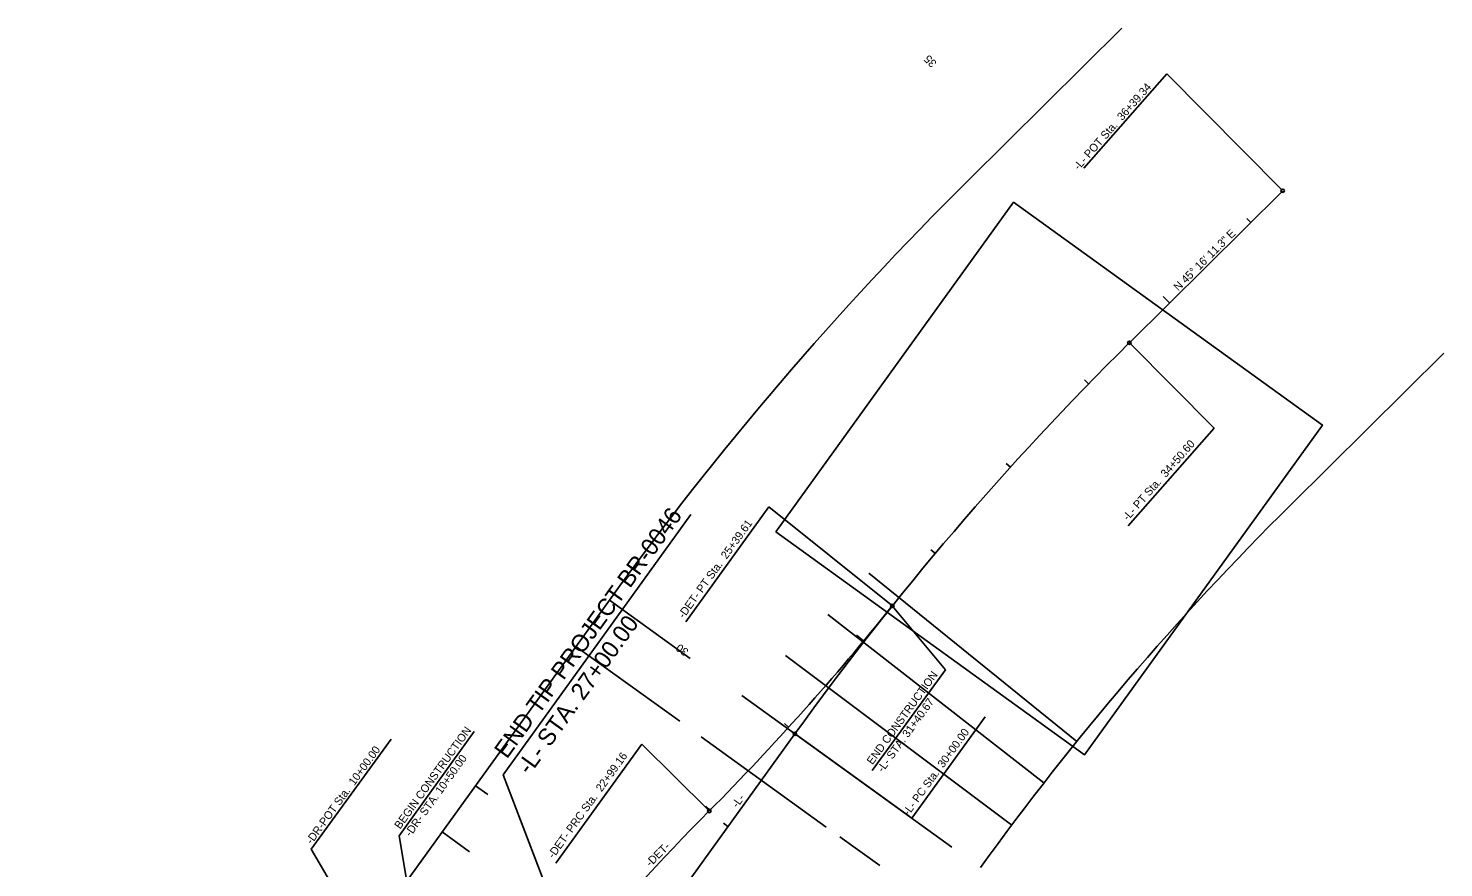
# Model space of a CAD drawing. Extents: x 2189281 to 2191267, y 386656 to 389012.
# Drawn here: x 2190029 to 2191267, y 388278 to 389012 of the extents above; entities that cross this region are included whole.
import ezdxf

# ---------------------------------------------------------------- set-up
doc = ezdxf.new("R2010")
doc.units = 0
for name, color, linetype in [('Prop DSN Text', 7, 'Continuous'), ('Prop Horizontal Alignment', 7, 'Continuous'), ('Prop Horizontal Alignment Direction Label', 7, 'Continuous'), ('Prop Horizontal Alignment Station Label', 7, 'Continuous'), ('Prop Horizontal Alignment Tick Label', 7, 'Continuous'), ('Prop Horizontal Alignment Tick Large', 7, 'Continuous'), ('Prop Horizontal Alignment Tick Small', 7, 'Continuous'), ('Scratch_Level_3', 7, 'Continuous'), ('Scratch_Level_5', 7, 'Continuous')]:
    doc.layers.add(name, color=color, linetype=linetype)

msp = doc.modelspace()

# ---------------------------------------------------------------- linework, layer by layer
at = {"layer": 'Prop DSN Text'}
for p, q in [((2190608.2, 388587.1), (2190444, 388359.4)), ((2190830.8, 388451.2), (2190784.4, 388507.2)), ((2190766.7, 388363.2), (2190830.8, 388451.2)), ((2190353.3, 388306), (2190418.9, 388397.4)), ((2190523.8, 388151.9), (2190444, 388359.4)), ((2190374.3, 388178.9), (2190353.3, 388306))]:
    msp.add_line(p, q, dxfattribs=at)
at = {"layer": 'Prop Horizontal Alignment'}
for p, q in [((2190991.7, 388737.3), (2191125.8, 388870.2)), ((2189529.4, 386773.1), (2190699.2, 388395.3))]:
    msp.add_line(p, q, dxfattribs=at)
for centre, radius, start, end in [((2192910.1, 386800.9), 2725.8, 134.7302, 144.2018), ((2188990.8, 389947), 2300, 315.255, 321.245), ((2192257.9, 386708.8), 2300, 135.255, 144.2018)]:
    msp.add_arc(centre, radius, start, end, dxfattribs=at)
at = {"layer": 'Prop Horizontal Alignment Station Label'}
for p, q in [((2190951.9, 388889.9), (2191024.5, 388972.5)), ((2191124.8, 388871.2), (2191024.5, 388972.5)), ((2190992.8, 388736.3), (2191065.8, 388662.6)), ((2190990.8, 388577.1), (2191065.8, 388662.6)), ((2190676.4, 388593.9), (2190603.8, 388493.2)), ((2190783.3, 388508.1), (2190676.4, 388593.9)), ((2190801.4, 388321.6), (2190865.6, 388410.3)), ((2190490.3, 388282.2), (2190565.3, 388386.4)), ((2190623.3, 388328.9), (2190565.3, 388386.4)), ((2190700.5, 388394.4), (2190801.4, 388321.6))]:
    msp.add_line(p, q, dxfattribs=at)
msp.add_lwpolyline([(2190330.1, 388202.3), (2190276.3, 388294.6), (2190346.2, 388390.8)], dxfattribs=at)
for centre in [(2191125.8, 388870.2), (2190991.7, 388737.3), (2190784.4, 388507.2), (2190699.2, 388395.3), (2190624.4, 388327.9)]:
    msp.add_circle(centre, 1.5, dxfattribs=at)
at = {"layer": 'Prop Horizontal Alignment Tick Large'}
for p, q in [((2191026.8, 388772.1), (2191021.2, 388777.8)), ((2190759.4, 388476.5), (2190753.2, 388481.6)), ((2190699.2, 388395.3), (2190692.7, 388400))]:
    msp.add_line(p, q, dxfattribs=at)
at = {"layer": 'Prop Horizontal Alignment Tick Small'}
for p, q in [((2191097.9, 388842.5), (2191094.4, 388846)), ((2190956.1, 388701.4), (2190952.5, 388704.9)), ((2190887.7, 388628.5), (2190884, 388631.8)), ((2190822.1, 388553.1), (2190818.2, 388556.3)), ((2190759.2, 388475.3), (2190755.3, 388478.4)), ((2190693.8, 388401), (2190690.1, 388404.4)), ((2190625, 388328.5), (2190621.4, 388332)), ((2190640.7, 388314.2), (2190636.7, 388317.1))]:
    msp.add_line(p, q, dxfattribs=at)
at = {"layer": 'Scratch_Level_3'}
msp.add_lwpolyline([(2190682.5, 388571.9), (2190890.4, 388860.2), (2191160.5, 388665.3), (2190952.6, 388377)], close=True, dxfattribs=at)
at = {"layer": 'Scratch_Level_5'}
for p, q in [((2190851, 388879.4), (2190985.1, 389012.3)), ((2191132.5, 388595.3), (2191266.6, 388728.1)), ((2190945.8, 388388.7), (2190763.8, 388535.8)), ((2189367.2, 386890.1), (2190537, 388512.3)), ((2190537, 388512.3), (2190607.7, 388461.3)), ((2190917, 388352.4), (2190727.9, 388499.6)), ((2190507.8, 388471.7), (2190598.5, 388406.3)), ((2190888.9, 388315.6), (2190691, 388463.9)), ((2190652.8, 388428.8), (2190836.6, 388296.2)), ((2190617.2, 388392.8), (2190726.7, 388313.8)), ((2190420, 388350), (2190430.8, 388342.2)), ((2190390.8, 388309.5), (2190414.8, 388292.2)), ((2190738.6, 388305.2), (2190773.4, 388280.1))]:
    msp.add_line(p, q, dxfattribs=at)
for radius in [2925.8, 2525.8]:
    msp.add_arc((2192910.1, 386800.9), radius, 134.7302, 144.2018, dxfattribs=at)

# ---------------------------------------------------------------- texts
at = {"layer": 'Prop DSN Text'}
for s, height, rotation, p in [('END TIP PROJECT BR-0046', 15, 54.2018, (2190447.4, 388372.8)), ('-L- STA. 27+00.00', 15, 54.2018, (2190467.2, 388358.6)), ('END CONSTRUCTION', 7, 53.9661, (2190767.1, 388367.8)), ('-L- STA. 31+40.67', 7, 53.9661, (2190776.2, 388361.2)), ('BEGIN CONSTRUCTION', 7, 54.2018, (2190354, 388311.5)), ('-DR- STA. 10+50.00', 7, 54.2018, (2190363.1, 388304.9)), ('-L-', 7, 54.2018, (2190649, 388330.1)), ('-DET-', 7, 44.6789, (2190572.8, 388278.6))]:
    msp.add_text(s, height=height, rotation=rotation, dxfattribs=at).set_placement(p)
at = {"layer": 'Prop Horizontal Alignment Direction Label'}
msp.add_text('N 45%%d 16\' 11.3" E', height=7, rotation=44.7302, dxfattribs=at).set_placement((2191034.5, 388782.1))
at = {"layer": 'Prop Horizontal Alignment Station Label'}
for s, rotation, p in [('-L- POT Sta.  36+39.34', 48.7114, (2190947.4, 388887.7)), ('-L- PT Sta.  34+50.60', 48.6794, (2190990.3, 388581.1)), ('-DET- PT Sta.  25+39.61', 54.2018, (2190602.1, 388495.7)), ('-L- PC Sta.  30+00.00', 53.9661, (2190798.7, 388323.4)), ('-DR-POT Sta.  10+00.00', 54.018, (2190276.7, 388298.3)), ('-DET- PRC Sta.  22+99.16', 54.2018, (2190488.2, 388285.9))]:
    msp.add_text(s, height=7, rotation=rotation, dxfattribs=at).set_placement(p)
at = {"layer": 'Prop Horizontal Alignment Tick Label'}
for s, rotation, p in [('35', 134.7302, (2190823.7, 388982.2)), ('30', 144.2018, (2190606.9, 388468.4))]:
    msp.add_text(s, height=7, rotation=rotation, dxfattribs=at).set_placement(p)

doc.saveas('drawing.dxf')
